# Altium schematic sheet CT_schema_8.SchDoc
size 405 x 220 mm
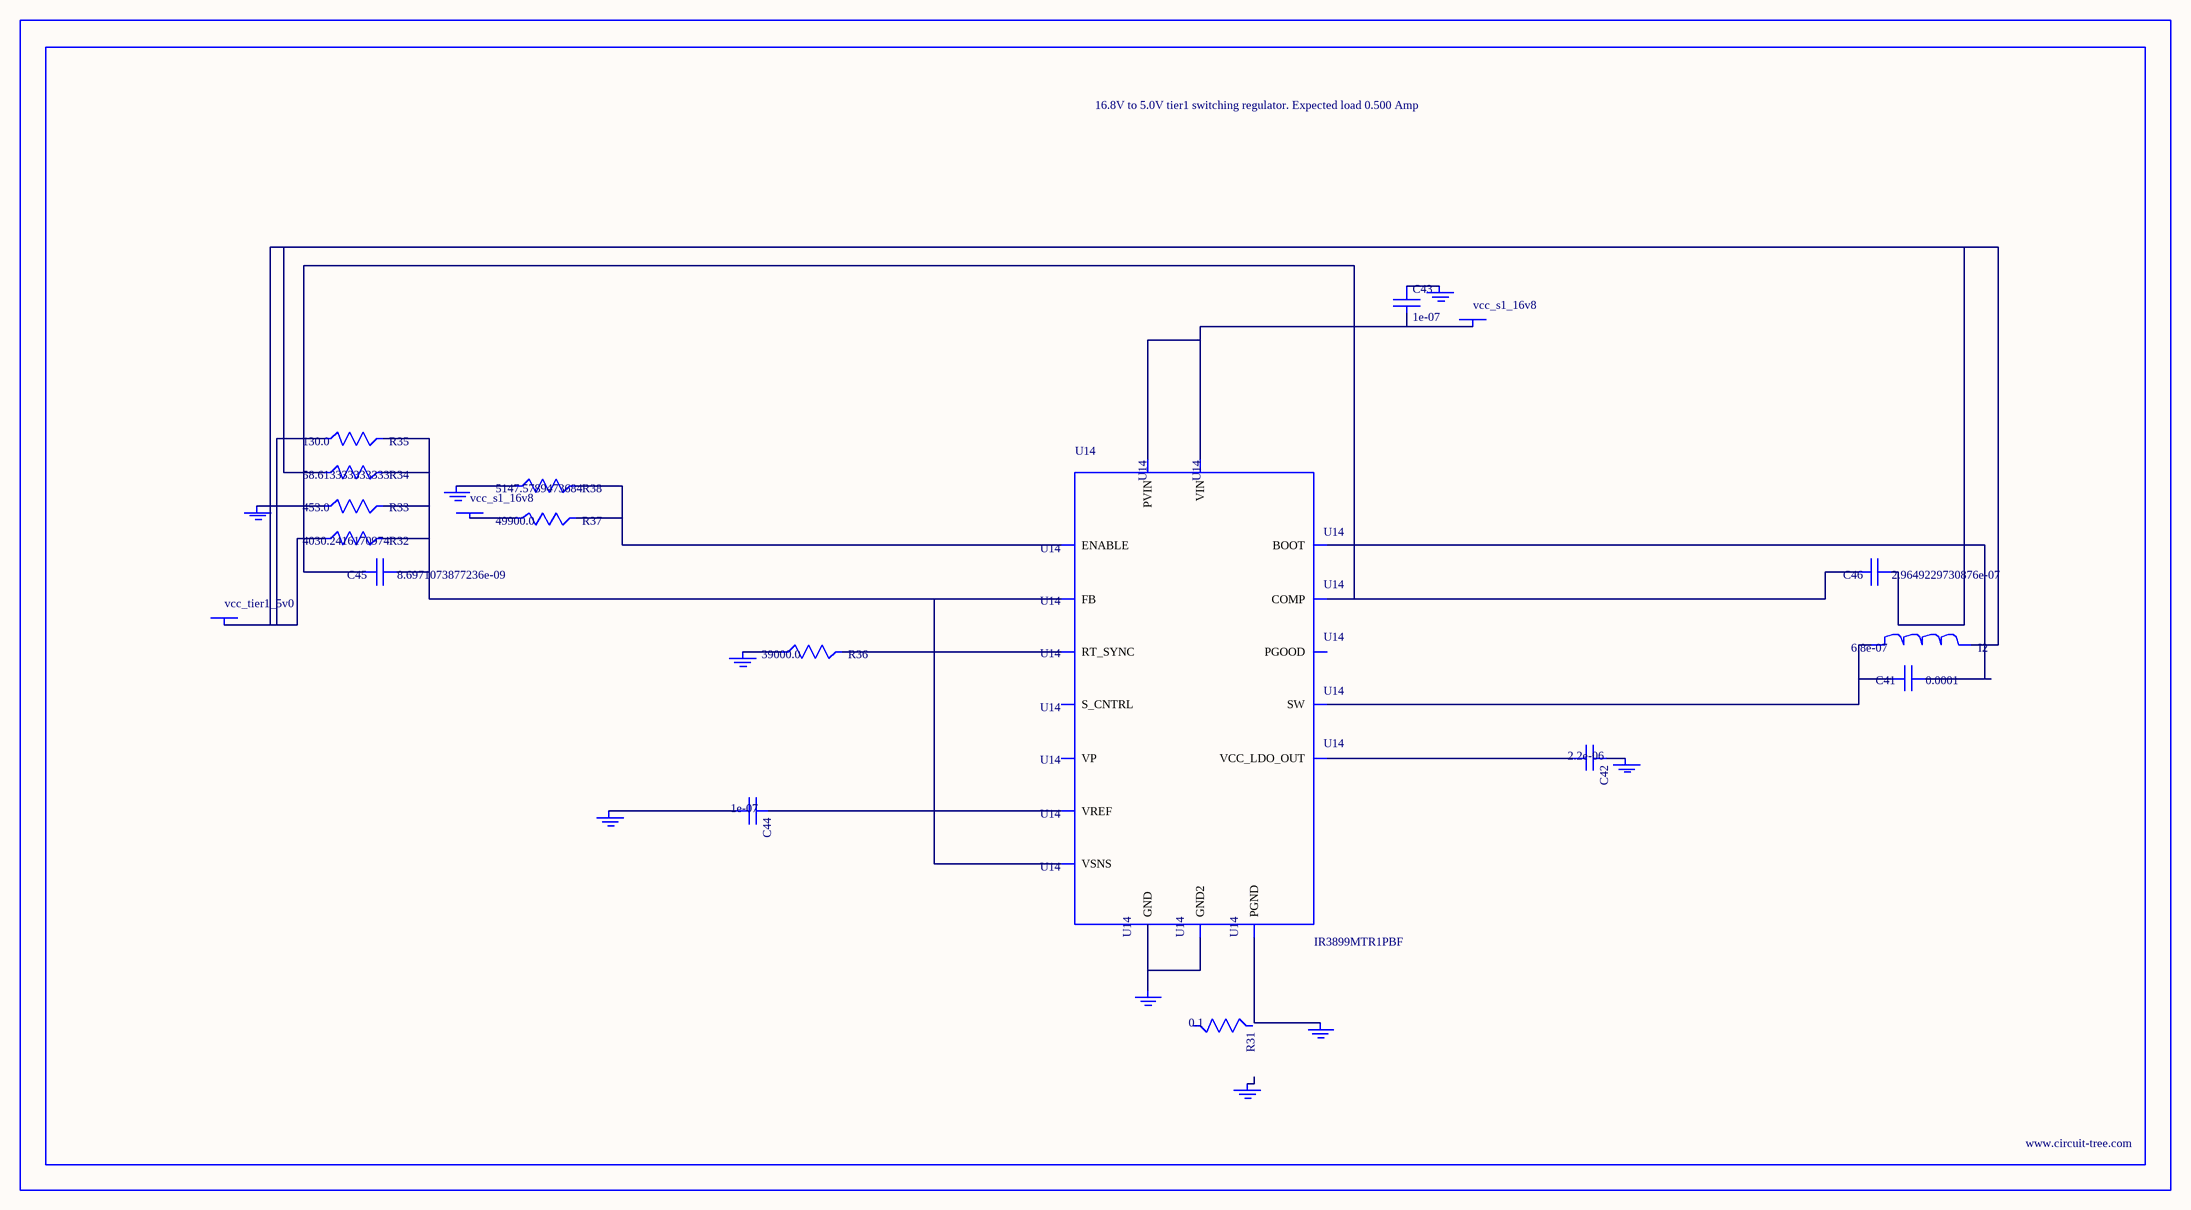
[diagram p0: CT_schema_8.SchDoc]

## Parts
BORDER7  (no value)
C41  0.0001  [C1210]
C42  2.2e-06  [C0603]
C43  1e-07  [C0402]
C44  1e-07  [C0402]
C45  8.6971073877236e-09  [R0603]
C46  2.9649229730876e-07  [R0603]
GND_INSTANCE_7_0  (no value)
GND_INSTANCE_7_1  (no value)
GND_INSTANCE_7_2  (no value)
GND_INSTANCE_7_3  (no value)
GND_INSTANCE_7_4  (no value)
GND_INSTANCE_7_5  (no value)
GND_INSTANCE_7_6  (no value)
GND_INSTANCE_7_7  (no value)
GND_INSTANCE_7_8  (no value)
I2  6.8e-07  [IND25X25CZ]
POWER_INSTANCE_7_0  vcc_s1_16v8
POWER_INSTANCE_7_1  vcc_s1_16v8
POWER_INSTANCE_7_2  vcc_tier1_5v0
R31  0.1  [R0603]
R32  4030.2416170974  [R0603]
R33  453.0  [R0603]
R34  58.613333333333  [R0603]
R35  130.0  [R0603]
R36  39000.0  [R0603]
R37  49900.0  [R0603]
R38  5147.5789473684  [R0603]
U14  IR3899MTR1PBF  [IR3899MTR1PBF]

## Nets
NetC41_1: C41.1 U14.14(BOOT)
NetC41_2: C41.2 I2.1 U14.12(SW)
NetC42_1: C42.1 GND_INSTANCE_7_4.0(GND)
NetC42_2: C42.2 U14.10(VCC_LDO_OUT)
NetC43_1: C43.1 GND_INSTANCE_7_3.0(GND)
NetC43_2: C43.2 POWER_INSTANCE_7_0.0(PWR) U14.9(VIN) U14.13(PVIN)
NetC44_1: C44.1 U14.2(VREF)
NetC44_2: C44.2 GND_INSTANCE_7_1.0(GND)
NetC45_1: C45.1 R32.2 R33.2 R34.2 R35.2 U14.1(FB) U14.8(VSNS)
NetC45_2: C45.2 C46.2 U14.3(COMP)
NetC46_1: C46.1 I2.2 POWER_INSTANCE_7_2.0(PWR) R32.1 R34.1 R35.1
NetGND_INSTANCE_7_0_0: GND_INSTANCE_7_0.0(GND) R33.1
NetGND_INSTANCE_7_2_0: GND_INSTANCE_7_2.0(GND) R36.1
NetGND_INSTANCE_7_6_0: GND_INSTANCE_7_6.0(GND) U14.11(PGND)
NetGND_INSTANCE_7_7_0: GND_INSTANCE_7_7.0(GND) R38.1
NetGND_INSTANCE_7_8_0: GND_INSTANCE_7_8.0(GND) U14.4(GND) U14.17(GND2)
NetPOWER_INSTANCE_7_1_0: POWER_INSTANCE_7_1.0(PWR) R37.1
NetR36_2: R36.2 U14.5(RT_SYNC)
NetR37_2: R37.2 R38.2 U14.15(ENABLE)

Not connected (* = marked no-connect by the designer): GND_INSTANCE_7_5 0(GND); R31 1 2; U14 6(S_CNTRL) 7(PGOOD) 16(VP)

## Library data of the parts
BORDER7 = BORDER_PAGE7
C41 = GRM32ER61A107ME20L
C42 = C0603C225K8RACTU
C43 C44 = C0402C104K3RACTU
C45 = C45
C46 = C46
GND_INSTANCE_7_0-GND_INSTANCE_7_8 = GND
I2 = IHLP2525CZERR68M01
POWER_INSTANCE_7_0-POWER_INSTANCE_7_2 = PWR
R31 = ERJ-3RSFR10V
R32 = R32
R33 = ERJ-3EKF4530V
R34 = R34
R35 = RC0603JR-07130RL
R36 = RC0603JR-0739KL
R37 = RC0603FR-0749K9
R38 = R38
